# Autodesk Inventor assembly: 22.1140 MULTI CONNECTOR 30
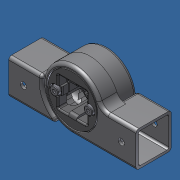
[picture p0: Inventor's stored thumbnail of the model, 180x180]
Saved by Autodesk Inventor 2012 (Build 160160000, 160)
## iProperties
Created: 2014-04
Part Number: 22.1140 MULTI CONNECTOR 30
Document SubType Name: Assembly
Designer: Admin
Author: Admin
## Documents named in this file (5)
- C:\Andys Backup Data\ANDY'S INVENTOR\INVENTOR LIBRARIES\PARTS LIBRARY\30 SERIES\22.1140 MULTI CONNECTOR 30.iam
- C:\Andys Backup Data\ANDY'S INVENTOR\INVENTOR LIBRARIES\PARTS LIBRARY\30 SERIES\SUBCOMPONENTS\22.1140 MULTI CONNECTOR 30 BODY.ipt
- C:\Andys Backup Data\ANDY'S INVENTOR\INVENTOR LIBRARIES\PARTS LIBRARY\FASTENING ELEMENTS\SCREWS CAP STAINLESS\21.1666 M8x10 Stainless.ipt
- C:\Andys Backup Data\ANDY'S INVENTOR\INVENTOR LIBRARIES\PARTS LIBRARY\30 SERIES\SUBCOMPONENTS\22.1140 MULTI CONNECTOR 30 INSERT.ipt
- C:\Andys Backup Data\ANDY'S INVENTOR\INVENTOR LIBRARIES\PARTS LIBRARY\FASTENING ELEMENTS\SCREWS CAP STAINLESS\21.1235_1 M5X16 SS.ipt
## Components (10 placed, 4 different names)
1. 22.1140 MULTI CONNECTOR 30 BODY:1 — Insert:1, Mate:1, Mate:2, Angle:1, Mate:5, Mate:7
2. 22.1140 MULTI CONNECTOR 30 BODY:2 — Insert:2, Mate:1, Mate:2, Angle:1, Mate:3, Mate:4
3. 21.1666 M8x10 Stainless ELH:1 — Insert:1
4. 21.1666 M8x10 Stainless ELH:2 — Insert:2
5. 22.1140 MULTI CONNECTOR 30 INSERT:1 — Mate:3, Mate:4, Mate:6, Insert:3, Insert:4
6. 22.1140 MULTI CONNECTOR 30 INSERT:2 — Mate:5, Mate:6, Mate:7, Insert:5, Insert:6
7. 21.1235_1  M5 x 16 SS:1 — Insert:3
8. 21.1235_1  M5 x 16 SS:2 — Insert:4
9. 21.1235_1  M5 x 16 SS:3 — Insert:5
10. 21.1235_1  M5 x 16 SS:4 — Insert:6
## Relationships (14: Mate 7, Insert 6, Angle 1)
- Insert:1: 22.1140 MULTI CONNECTOR 30 BODY:1 ↔ 21.1666 M8x10 Stainless ELH:1
- Insert:2: 22.1140 MULTI CONNECTOR 30 BODY:2 ↔ 21.1666 M8x10 Stainless ELH:2
- Mate:1: 22.1140 MULTI CONNECTOR 30 BODY:1 ↔ 22.1140 MULTI CONNECTOR 30 BODY:2
- Mate:2: 22.1140 MULTI CONNECTOR 30 BODY:1 ↔ 22.1140 MULTI CONNECTOR 30 BODY:2
- Angle:1: 22.1140 MULTI CONNECTOR 30 BODY:1 ↔ 22.1140 MULTI CONNECTOR 30 BODY:2
- Mate:3: 22.1140 MULTI CONNECTOR 30 BODY:2 ↔ 22.1140 MULTI CONNECTOR 30 INSERT:1
- Mate:4: 22.1140 MULTI CONNECTOR 30 BODY:2 ↔ 22.1140 MULTI CONNECTOR 30 INSERT:1
- Mate:5: 22.1140 MULTI CONNECTOR 30 BODY:1 ↔ 22.1140 MULTI CONNECTOR 30 INSERT:2
- Mate:6: 22.1140 MULTI CONNECTOR 30 INSERT:1 ↔ 22.1140 MULTI CONNECTOR 30 INSERT:2
- Mate:7: 22.1140 MULTI CONNECTOR 30 BODY:1 ↔ 22.1140 MULTI CONNECTOR 30 INSERT:2
- Insert:3: 22.1140 MULTI CONNECTOR 30 INSERT:1 ↔ 21.1235_1  M5 x 16 SS:1
- Insert:4: 22.1140 MULTI CONNECTOR 30 INSERT:1 ↔ 21.1235_1  M5 x 16 SS:2
- Insert:5: 22.1140 MULTI CONNECTOR 30 INSERT:2 ↔ 21.1235_1  M5 x 16 SS:3
- Insert:6: 22.1140 MULTI CONNECTOR 30 INSERT:2 ↔ 21.1235_1  M5 x 16 SS:4
